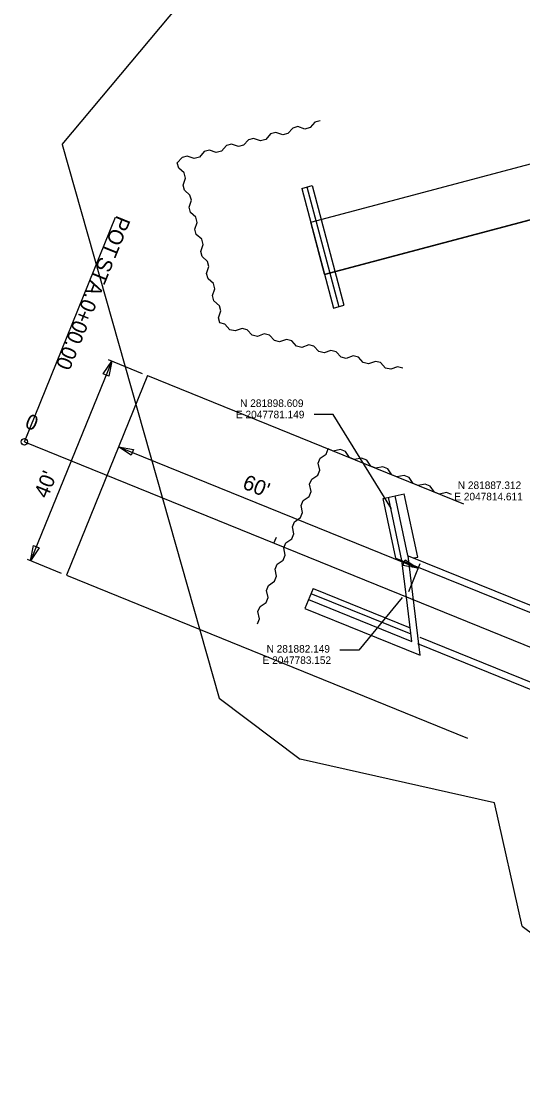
# Model space of a CAD drawing. Extents: x 2047712 to 2051245, y 280285 to 283042.
# Drawn here: x 2047712.4 to 2047805.5, y 281793.2 to 281989.1 of the extents above; entities that cross this region are included whole.
import ezdxf

# ---------------------------------------------------------------- set-up
doc = ezdxf.new("R2010")
doc.units = 0
for name, color, linetype in [('GE_P_Alignment', 7, 'Continuous'), ('RD_X_Cells', 7, 'Continuous'), ('RD_X_Concrete_Pad', 7, 'Continuous'), ('RD_X_GR_Rt', 7, 'Continuous'), ('RW_X_CL_100_Curve_Data', 7, 'Continuous'), ('RW_X_Esmt_SH', 7, 'Continuous'), ('SC_Scratch1', 7, 'Continuous'), ('SH_Data', 7, 'Continuous'), ('SV_Control_Point', 7, 'Continuous'), ('TopoDOT_Transients', 7, 'Continuous')]:
    doc.layers.add(name, color=color, linetype=linetype)

msp = doc.modelspace()

# ---------------------------------------------------------------- linework, layer by layer
at = {"layer": 'GE_P_Alignment'}
msp.add_line((2047712.98, 281911.04), (2047729.91, 281952.74), dxfattribs=at)
msp.add_circle((2047712.98, 281911.04), 0.6, dxfattribs=at)
at = {"layer": 'RD_X_Cells'}
for p, q in [((2047712.98, 281911.04), (2047713.73, 281912.89)), ((2047759.31, 281892.24), (2047759.76, 281893.35))]:
    msp.add_line(p, q, dxfattribs=at)
at = {"layer": 'RD_X_Concrete_Pad'}
for p, q in [((2047770.29, 281916.12), (2047766.77, 281916.12)), ((2047781.15, 281898.61), (2047770.29, 281916.12)), ((2047783.15, 281882.15), (2047775.06, 281872.36)), ((2047775.06, 281872.36), (2047771.54, 281872.36))]:
    msp.add_line(p, q, dxfattribs=at)
at = {"layer": 'RD_X_GR_Rt'}
for p, q in [((2047729.2, 281926.04), (2047714.15, 281888.98)), ((2047728.52, 281926.32), (2047734.85, 281923.75)), ((2047735.82, 281923.35), (2047720.78, 281886.29)), ((2047735.82, 281923.35), (2047794.52, 281899.53)), ((2047730.46, 281910.15), (2047786.05, 281887.58)), ((2047713.48, 281889.25), (2047719.81, 281886.68)), ((2047786.39, 281888.4), (2047784.28, 281883.21)), ((2047720.78, 281886.29), (2047795.25, 281856.06))]:
    msp.add_line(p, q, dxfattribs=at)
for points in [[(2047728.66, 281923.24), (2047727.62, 281923.66), (2047729.2, 281926.04)], [(2047733.27, 281909.61), (2047732.84, 281908.58), (2047730.46, 281910.15)], [(2047714.69, 281891.79), (2047715.72, 281891.37), (2047714.15, 281888.98)], [(2047783.25, 281888.12), (2047783.67, 281889.15), (2047786.05, 281887.58)]]:
    msp.add_lwpolyline(points, close=True, dxfattribs=at)
at = {"layer": 'RW_X_CL_100_Curve_Data'}
for p, q in [((2047766.15, 281951.84), (2047882.13, 281982.63)), ((2047766.15, 281951.82), (2047882.13, 281982.62)), ((2047768.72, 281942.16), (2047884.7, 281972.95)), ((2047768.72, 281942.14), (2047884.7, 281972.93)), ((2047764.48, 281958.1), (2047766.42, 281958.62)), ((2047765.45, 281958.36), (2047771.35, 281936.13)), ((2047766.42, 281958.62), (2047772.32, 281936.39)), ((2047764.48, 281958.1), (2047770.38, 281935.87)), ((2047768.72, 281942.16), (2047766.15, 281951.82)), ((2047770.38, 281935.87), (2047772.32, 281936.39))]:
    msp.add_line(p, q, dxfattribs=at)
at = {"layer": 'RW_X_Esmt_SH'}
for p, q in [((2047766.91, 281970.39), (2047766.02, 281969.38)), ((2047767.88, 281970.65), (2047766.91, 281970.39)), ((2047758.7, 281968.21), (2047757.8, 281967.19)), ((2047759.66, 281968.46), (2047758.7, 281968.21)), ((2047760.94, 281968.03), (2047759.66, 281968.46)), ((2047761.91, 281968.29), (2047760.94, 281968.03)), ((2047762.8, 281969.3), (2047761.91, 281968.29)), ((2047763.77, 281969.56), (2047762.8, 281969.3)), ((2047765.05, 281969.12), (2047763.77, 281969.56)), ((2047766.02, 281969.38), (2047765.05, 281969.12)), ((2047750.48, 281966.03), (2047749.59, 281965.01)), ((2047751.45, 281966.28), (2047750.48, 281966.03)), ((2047752.73, 281965.85), (2047751.45, 281966.28)), ((2047753.69, 281966.1), (2047752.73, 281965.85)), ((2047754.59, 281967.12), (2047753.69, 281966.1)), ((2047755.55, 281967.37), (2047754.59, 281967.12)), ((2047756.83, 281966.94), (2047755.55, 281967.37)), ((2047757.8, 281967.19), (2047756.83, 281966.94)), ((2047743.23, 281964.1), (2047742.26, 281963.85)), ((2047744.51, 281963.67), (2047743.23, 281964.1)), ((2047746.37, 281964.94), (2047745.48, 281963.92)), ((2047747.34, 281965.19), (2047746.37, 281964.94)), ((2047748.62, 281964.76), (2047747.34, 281965.19)), ((2047749.59, 281965.01), (2047748.62, 281964.76)), ((2047742.26, 281963.85), (2047741.37, 281962.83)), ((2047741.63, 281961.87), (2047741.37, 281962.83)), ((2047745.48, 281963.92), (2047744.51, 281963.67)), ((2047742.64, 281960.97), (2047741.63, 281961.87)), ((2047742.9, 281960), (2047742.64, 281960.97)), ((2047742.46, 281958.72), (2047742.9, 281960)), ((2047742.72, 281957.76), (2047742.46, 281958.72)), ((2047743.73, 281956.86), (2047742.72, 281957.76)), ((2047743.99, 281955.9), (2047743.73, 281956.86)), ((2047743.55, 281954.62), (2047743.99, 281955.9)), ((2047743.81, 281953.65), (2047743.55, 281954.62)), ((2047744.82, 281952.76), (2047743.81, 281953.65)), ((2047745.08, 281951.79), (2047744.82, 281952.76)), ((2047744.64, 281950.51), (2047745.08, 281951.79)), ((2047744.9, 281949.54), (2047744.64, 281950.51)), ((2047745.91, 281948.65), (2047744.9, 281949.54)), ((2047746.17, 281947.68), (2047745.91, 281948.65)), ((2047745.73, 281946.4), (2047746.17, 281947.68)), ((2047745.99, 281945.43), (2047745.73, 281946.4)), ((2047747, 281944.54), (2047745.99, 281945.43)), ((2047747.26, 281943.57), (2047747, 281944.54)), ((2047746.82, 281942.29), (2047747.26, 281943.57)), ((2047747.08, 281941.33), (2047746.82, 281942.29)), ((2047748.09, 281940.43), (2047747.08, 281941.33)), ((2047747.91, 281938.19), (2047748.35, 281939.47)), ((2047748.35, 281939.47), (2047748.09, 281940.43)), ((2047748.17, 281937.22), (2047747.91, 281938.19)), ((2047749.18, 281936.32), (2047748.17, 281937.22)), ((2047749, 281934.08), (2047749.44, 281935.36)), ((2047749.44, 281935.36), (2047749.18, 281936.32)), ((2047749.26, 281933.11), (2047749, 281934.08)), ((2047750.23, 281932.87), (2047749.26, 281933.11)), ((2047751.14, 281931.87), (2047750.23, 281932.87)), ((2047752.12, 281931.63), (2047751.14, 281931.87)), ((2047753.39, 281932.09), (2047752.12, 281931.63)), ((2047754.36, 281931.85), (2047753.39, 281932.09)), ((2047755.27, 281930.86), (2047754.36, 281931.85)), ((2047756.24, 281930.62), (2047755.27, 281930.86)), ((2047757.51, 281931.08), (2047756.24, 281930.62)), ((2047758.48, 281930.84), (2047757.51, 281931.08)), ((2047759.4, 281929.84), (2047758.48, 281930.84)), ((2047760.37, 281929.6), (2047759.4, 281929.84)), ((2047761.64, 281930.06), (2047760.37, 281929.6)), ((2047762.61, 281929.82), (2047761.64, 281930.06)), ((2047763.52, 281928.82), (2047762.61, 281929.82)), ((2047764.49, 281928.58), (2047763.52, 281928.82)), ((2047765.77, 281929.04), (2047764.49, 281928.58)), ((2047766.74, 281928.8), (2047765.77, 281929.04)), ((2047767.65, 281927.8), (2047766.74, 281928.8)), ((2047768.62, 281927.56), (2047767.65, 281927.8)), ((2047769.89, 281928.02), (2047768.62, 281927.56)), ((2047770.86, 281927.78), (2047769.89, 281928.02)), ((2047771.78, 281926.78), (2047770.86, 281927.78)), ((2047772.75, 281926.54), (2047771.78, 281926.78)), ((2047774.02, 281927), (2047772.75, 281926.54)), ((2047774.99, 281926.76), (2047774.02, 281927)), ((2047775.9, 281925.77), (2047774.99, 281926.76)), ((2047776.87, 281925.53), (2047775.9, 281925.77)), ((2047778.15, 281925.99), (2047776.87, 281925.53)), ((2047779.12, 281925.75), (2047778.15, 281925.99)), ((2047780.03, 281924.75), (2047779.12, 281925.75)), ((2047782.27, 281924.97), (2047781, 281924.51)), ((2047783.24, 281924.73), (2047782.27, 281924.97)), ((2047781, 281924.51), (2047780.03, 281924.75))]:
    msp.add_line(p, q, dxfattribs=at)
at = {"layer": 'SC_Scratch1'}
msp.add_line((2047712.98, 281911.04), (2047990.95, 281798.21), dxfattribs=at)
at = {"layer": 'SH_Data'}
for p, q in [((2047779.61, 281900.56), (2047783.52, 281901.39)), ((2047786, 281889.65), (2047783.52, 281901.39)), ((2047781.95, 281889.48), (2047779.61, 281900.56)), ((2047783.07, 281889.03), (2047780.59, 281900.77)), ((2047784.16, 281889.93), (2047781.81, 281901.02)), ((2047786.47, 281871.46), (2047784.22, 281889.91)), ((2047784.22, 281889.91), (2047919.12, 281835.19)), ((2047785.26, 281889.49), (2047786, 281889.65)), ((2047781.95, 281889.48), (2047919.29, 281833.77)), ((2047783.9, 281882.21), (2047783.07, 281889.03)), ((2047766.57, 281883.85), (2047765.07, 281880.14)), ((2047766.57, 281883.85), (2047784.59, 281876.54)), ((2047765.72, 281881.76), (2047784.9, 281873.98)), ((2047766.19, 281882.92), (2047784.73, 281875.4)), ((2047784.9, 281873.98), (2047783.9, 281882.21)), ((2047765.07, 281880.14), (2047786.47, 281871.46)), ((2047920.95, 281820.15), (2047786.48, 281874.73)), ((2047920.48, 281818.99), (2047786.01, 281873.57))]:
    msp.add_line(p, q, dxfattribs=at)
at = {"layer": 'SV_Control_Point'}
for p, q in [((2047720.03, 281966.22), (2047749.13, 281863.47)), ((2047749.13, 281863.47), (2047764.17, 281852.16)), ((2047805.42, 281821.12), (2047850.83, 281786.96))]:
    msp.add_line(p, q, dxfattribs=at)
for points in [[(2047720.03, 281966.22), (2047776.38, 282033.57), (2047764.62, 282142.83)], [(2047805.42, 281821.12), (2047800.29, 281844.03), (2047764.17, 281852.16)]]:
    msp.add_lwpolyline(points, dxfattribs=at)
at = {"layer": 'TopoDOT_Transients'}
for p, q in [((2047769.04, 281908.79), (2047769.41, 281909.72)), ((2047770.34, 281909.34), (2047769.41, 281909.72)), ((2047771.66, 281909.62), (2047770.34, 281909.34)), ((2047772.59, 281909.24), (2047771.66, 281909.62)), ((2047773.35, 281908.12), (2047772.59, 281909.24)), ((2047767.54, 281907.11), (2047767.92, 281908.03)), ((2047767.92, 281908.03), (2047769.04, 281908.79)), ((2047774.28, 281907.75), (2047773.35, 281908.12)), ((2047775.6, 281908.02), (2047774.28, 281907.75)), ((2047776.53, 281907.64), (2047775.6, 281908.02)), ((2047777.29, 281906.52), (2047776.53, 281907.64)), ((2047767.44, 281904.86), (2047767.81, 281905.78)), ((2047767.81, 281905.78), (2047767.54, 281907.11)), ((2047778.21, 281906.15), (2047777.29, 281906.52)), ((2047779.54, 281906.42), (2047778.21, 281906.15)), ((2047780.47, 281906.04), (2047779.54, 281906.42)), ((2047781.23, 281904.92), (2047780.47, 281906.04)), ((2047765.94, 281903.17), (2047766.32, 281904.1)), ((2047766.32, 281904.1), (2047767.44, 281904.86)), ((2047782.15, 281904.55), (2047781.23, 281904.92)), ((2047783.48, 281904.82), (2047782.15, 281904.55)), ((2047784.4, 281904.44), (2047783.48, 281904.82)), ((2047785.16, 281903.33), (2047784.4, 281904.44)), ((2047786.09, 281902.95), (2047785.16, 281903.33)), ((2047765.84, 281900.92), (2047766.21, 281901.84)), ((2047766.21, 281901.84), (2047765.94, 281903.17)), ((2047787.41, 281903.22), (2047786.09, 281902.95)), ((2047788.34, 281902.85), (2047787.41, 281903.22)), ((2047789.1, 281901.73), (2047788.34, 281902.85)), ((2047790.03, 281901.35), (2047789.1, 281901.73)), ((2047791.35, 281901.62), (2047790.03, 281901.35)), ((2047792.28, 281901.25), (2047791.35, 281901.62)), ((2047764.34, 281899.23), (2047764.72, 281900.16)), ((2047764.72, 281900.16), (2047765.84, 281900.92)), ((2047764.24, 281896.98), (2047764.62, 281897.91)), ((2047764.62, 281897.91), (2047764.34, 281899.23)), ((2047762.75, 281895.29), (2047763.12, 281896.22)), ((2047763.12, 281896.22), (2047764.24, 281896.98)), ((2047762.64, 281893.04), (2047763.02, 281893.97)), ((2047763.02, 281893.97), (2047762.75, 281895.29)), ((2047761.15, 281891.35), (2047761.52, 281892.28)), ((2047761.52, 281892.28), (2047762.64, 281893.04)), ((2047761.04, 281889.1), (2047761.42, 281890.03)), ((2047761.42, 281890.03), (2047761.15, 281891.35)), ((2047759.55, 281887.42), (2047759.93, 281888.34)), ((2047759.93, 281888.34), (2047761.04, 281889.1)), ((2047759.44, 281885.17), (2047759.82, 281886.09)), ((2047759.82, 281886.09), (2047759.55, 281887.42)), ((2047757.95, 281883.48), (2047758.33, 281884.41)), ((2047758.33, 281884.41), (2047759.44, 281885.17)), ((2047757.85, 281881.23), (2047758.22, 281882.15)), ((2047758.22, 281882.15), (2047757.95, 281883.48)), ((2047756.35, 281879.54), (2047756.73, 281880.47)), ((2047756.73, 281880.47), (2047757.85, 281881.23)), ((2047756.25, 281877.29), (2047756.62, 281878.22)), ((2047756.62, 281878.22), (2047756.35, 281879.54))]:
    msp.add_line(p, q, dxfattribs=at)

# ---------------------------------------------------------------- texts
at = {"layer": 'GE_P_Alignment'}
for s, p in [('POT', (2047730.16, 281953.24)), (' STA. ', (2047727.45, 281946.57)), ('0+00.00', (2047723.89, 281937.81))]:
    msp.add_text(s, height=2.8, rotation=247.9067, dxfattribs=at).set_placement(p)
at = {"layer": 'RD_X_Cells'}
msp.add_text('0', height=2.8, rotation=337.9067, dxfattribs=at).set_placement((2047712.89, 281913.78))
at = {"layer": 'RD_X_Concrete_Pad'}
for s, p in [('N 281898.609', (2047753.04, 281917.52)), ('E 2047781.149', (2047752.27, 281915.42)), ('N 281887.312', (2047793.45, 281902.29)), ('E 2047814.611', (2047792.8, 281900.19)), ('N 281882.149', (2047757.95, 281871.92)), ('E 2047783.152', (2047757.22, 281869.82))]:
    msp.add_text(s, height=1.4, dxfattribs=at).set_placement(p)
at = {"layer": 'RD_X_GR_Rt'}
for s, rotation, p in [("40'", 67.9067, (2047717.27, 281900.38)), ("60'", 337.9067, (2047753.29, 281902.47))]:
    msp.add_text(s, height=2.8, rotation=rotation, dxfattribs=at).set_placement(p)

doc.saveas('drawing.dxf')
